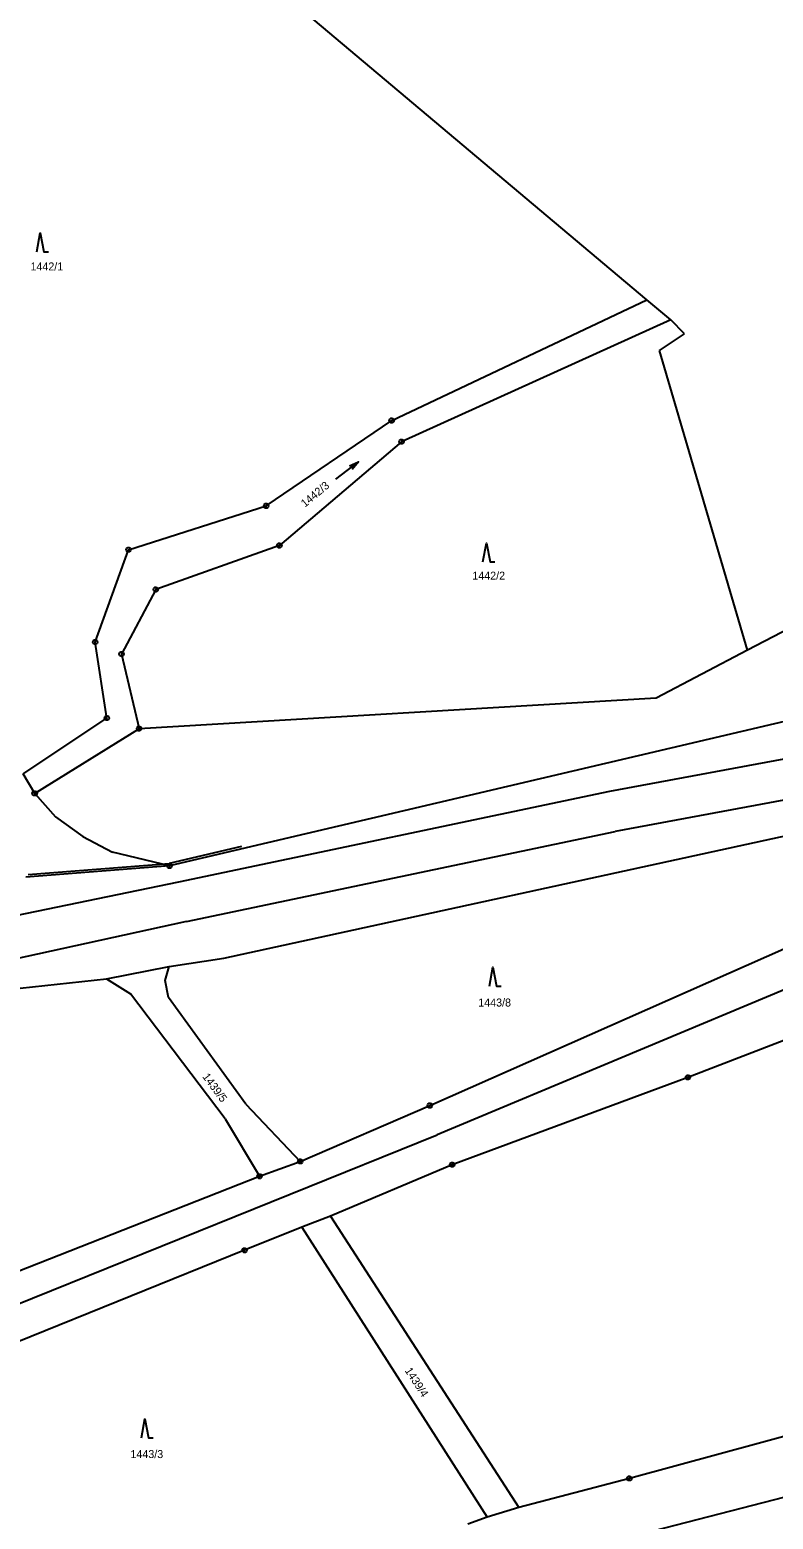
# Model space of a CAD drawing. Extents: x -779618 to -776429, y -1144546 to -1143350.
# Drawn here: x -779036.4 to -778878.5, y -1144107.3 to -1143790.9 of the extents above; entities that cross this region are included whole.
import ezdxf

# ---------------------------------------------------------------- set-up
doc = ezdxf.new("R2010")
doc.units = 0
for name, color, linetype in [('1', 7, 'Continuous'), ('2', 7, 'Continuous'), ('3', 7, 'Continuous'), ('4', 7, 'Continuous'), ('6', 7, 'Continuous'), ('8', 7, 'Continuous')]:
    doc.layers.add(name, color=color, linetype=linetype)

msp = doc.modelspace()

# ---------------------------------------------------------------- linework, layer by layer
at = {"layer": '1'}
for p, q in [((-778905.32, -1143848.25), (-779024.41, -1143748.09)), ((-778959.55, -1143873.91), (-778905.32, -1143848.25)), ((-778900.27, -1143852.49), (-778905.32, -1143848.25)), ((-778900.27, -1143852.49), (-778957.45, -1143878.42)), ((-778897.33, -1143855.5), (-778900.27, -1143852.49)), ((-778902.68, -1143859.04), (-778897.33, -1143855.5)), ((-778883.94, -1143922.67), (-778902.68, -1143859.04)), ((-778986.2, -1143892.04), (-778959.55, -1143873.91)), ((-778957.45, -1143878.42), (-778983.4, -1143900.47)), ((-779015.46, -1143901.34), (-778986.2, -1143892.04)), ((-778983.4, -1143900.47), (-779009.67, -1143909.81)), ((-779022.54, -1143920.99), (-779015.46, -1143901.34)), ((-779009.67, -1143909.81), (-779016.93, -1143923.52)), ((-778859.79, -1143910.12), (-778883.94, -1143922.67)), ((-779020.06, -1143937.12), (-779022.54, -1143920.99)), ((-778883.94, -1143922.67), (-778903.35, -1143932.91)), ((-779016.93, -1143923.52), (-779013.21, -1143939.37)), ((-778853.06, -1143932.41), (-779006.75, -1143968.53)), ((-778903.35, -1143932.91), (-779013.21, -1143939.37)), ((-779037.83, -1143948.95), (-779020.06, -1143937.12)), ((-779013.21, -1143939.37), (-779035.38, -1143953.12)), ((-779035.38, -1143953.12), (-779037.83, -1143948.95)), ((-779035.38, -1143953.12), (-779030.98, -1143958.09)), ((-779030.98, -1143958.09), (-779025.16, -1143962.28)), ((-779025.16, -1143962.28), (-779018.83, -1143965.62)), ((-778995.21, -1143988.16), (-778873.05, -1143961.47)), ((-779006.75, -1143968.53), (-779018.83, -1143965.62)), ((-779006.75, -1143968.53), (-779037.25, -1143970.89)), ((-778951.45, -1144019.43), (-778858.72, -1143978.35)), ((-779006.83, -1143989.87), (-778995.21, -1143988.16)), ((-779038.48, -1143994.53), (-779020.16, -1143992.5)), ((-779020.16, -1143992.5), (-779006.83, -1143989.87)), ((-779020.16, -1143992.5), (-779015.01, -1143995.67)), ((-779007.66, -1143992.86), (-779006.83, -1143989.87)), ((-778994.91, -1144022.25), (-779015.01, -1143995.67)), ((-779006.98, -1143996.49), (-779007.66, -1143992.86)), ((-778990.55, -1144019.15), (-779006.98, -1143996.49)), ((-778852.71, -1143996.58), (-778896.61, -1144013.46)), ((-778896.61, -1144013.46), (-778946.7, -1144032.01)), ((-778990.55, -1144019.15), (-778978.96, -1144031.32)), ((-778978.96, -1144031.32), (-778951.45, -1144019.43)), ((-778994.91, -1144022.25), (-778987.6, -1144034.47)), ((-778987.6, -1144034.47), (-778978.96, -1144031.32)), ((-778946.7, -1144032.01), (-778972.53, -1144042.97)), ((-779044.42, -1144056.76), (-778987.6, -1144034.47)), ((-778972.53, -1144042.97), (-778978.64, -1144045.3)), ((-778972.53, -1144042.97), (-778932.54, -1144104.86)), ((-778978.64, -1144045.3), (-778990.79, -1144050.19)), ((-778978.64, -1144045.3), (-778939.23, -1144106.88)), ((-778990.79, -1144050.19), (-779039.08, -1144069.74)), ((-778843.23, -1144080.83), (-778909.06, -1144098.66)), ((-778909.06, -1144098.66), (-778932.54, -1144104.86)), ((-778947.15, -1144120.83), (-778870.04, -1144101.07)), ((-778932.54, -1144104.86), (-778939.23, -1144106.88)), ((-778939.23, -1144106.88), (-778943.37, -1144108.37))]:
    msp.add_line(p, q, dxfattribs=at)
at = {"layer": '3'}
msp.add_line((-778971.41, -1143886.33), (-778966.63, -1143882.71), dxfattribs=at)
for points in [[(-779034.96, -1143838.03), (-779034.21, -1143834.03), (-779033.46, -1143838.03), (-779032.46, -1143838.03)], [(-778968.52, -1143883.52), (-778966.63, -1143882.71), (-778967.92, -1143884.32)], [(-778940.15, -1143903.95), (-778939.4, -1143899.95), (-778938.65, -1143903.95), (-778937.65, -1143903.95)], [(-778938.8, -1143994.05), (-778938.05, -1143990.05), (-778937.3, -1143994.05), (-778936.3, -1143994.05)], [(-779012.73, -1144090.02), (-779011.98, -1144086.02), (-779011.23, -1144090.02), (-779010.23, -1144090.02)]]:
    msp.add_lwpolyline(points, dxfattribs=at)
at = {"layer": '4'}
for p, q in [((-778826.44, -1143936.63), (-778913.28, -1143952.75)), ((-778824.89, -1143944.99), (-778912.1, -1143961.18)), ((-778913.28, -1143952.75), (-779004.84, -1143972.01)), ((-779003.12, -1143980.33), (-778912.1, -1143961.18)), ((-778991.42, -1143964.41), (-779006.83, -1143968.03)), ((-779036.75, -1143970.35), (-779006.83, -1143968.03)), ((-779004.84, -1143972.01), (-779044.16, -1143980.12)), ((-779003.12, -1143980.33), (-779039.97, -1143988.41))]:
    msp.add_line(p, q, dxfattribs=at)
at = {"layer": '6'}
for p in [(-778823.57, -1143972.84), (-779101.7, -1144086.88)]:
    msp.add_line(p, (-778949.91, -1144025.67), dxfattribs=at)
at = {"layer": '8'}
for p, q in [((-778959.67, -1143873.91), (-778959.43, -1143873.91)), ((-778957.57, -1143878.42), (-778957.33, -1143878.42)), ((-778986.32, -1143892.04), (-778986.08, -1143892.04)), ((-778983.52, -1143900.47), (-778983.28, -1143900.47)), ((-779015.58, -1143901.34), (-779015.34, -1143901.34)), ((-779009.79, -1143909.81), (-779009.55, -1143909.81)), ((-779022.66, -1143920.99), (-779022.42, -1143920.99)), ((-779017.05, -1143923.52), (-779016.81, -1143923.52)), ((-779020.18, -1143937.12), (-779019.94, -1143937.12)), ((-779013.33, -1143939.37), (-779013.09, -1143939.37)), ((-779035.5, -1143953.12), (-779035.26, -1143953.12)), ((-779006.87, -1143968.53), (-779006.63, -1143968.53)), ((-778896.73, -1144013.46), (-778896.49, -1144013.46)), ((-778951.57, -1144019.43), (-778951.33, -1144019.43)), ((-778979.08, -1144031.32), (-778978.84, -1144031.32)), ((-778946.82, -1144032.01), (-778946.58, -1144032.01)), ((-778987.72, -1144034.47), (-778987.48, -1144034.47)), ((-778990.91, -1144050.19), (-778990.67, -1144050.19)), ((-778909.18, -1144098.66), (-778908.94, -1144098.66))]:
    msp.add_line(p, q, dxfattribs=at)
for points in [[(-778959.4, -1143873.43), (-778959.15, -1143873.61), (-778959.05, -1143873.9), (-778959.15, -1143874.19), (-778959.4, -1143874.37), (-778959.71, -1143874.37), (-778959.96, -1143874.19), (-778960.06, -1143873.9), (-778959.96, -1143873.61), (-778959.71, -1143873.43)], [(-778957.3, -1143877.94), (-778957.05, -1143878.12), (-778956.95, -1143878.41), (-778957.05, -1143878.7), (-778957.3, -1143878.88), (-778957.61, -1143878.88), (-778957.86, -1143878.7), (-778957.96, -1143878.41), (-778957.86, -1143878.12), (-778957.61, -1143877.94)], [(-778986.05, -1143891.56), (-778985.8, -1143891.74), (-778985.7, -1143892.03), (-778985.8, -1143892.32), (-778986.05, -1143892.5), (-778986.36, -1143892.5), (-778986.61, -1143892.32), (-778986.71, -1143892.03), (-778986.61, -1143891.74), (-778986.36, -1143891.56)], [(-778983.25, -1143899.99), (-778983, -1143900.17), (-778982.9, -1143900.46), (-778983, -1143900.75), (-778983.25, -1143900.93), (-778983.56, -1143900.93), (-778983.81, -1143900.75), (-778983.91, -1143900.46), (-778983.81, -1143900.17), (-778983.56, -1143899.99)], [(-779015.31, -1143900.86), (-779015.06, -1143901.04), (-779014.96, -1143901.33), (-779015.06, -1143901.62), (-779015.31, -1143901.8), (-779015.62, -1143901.8), (-779015.87, -1143901.62), (-779015.97, -1143901.33), (-779015.87, -1143901.04), (-779015.62, -1143900.86)], [(-779009.52, -1143909.33), (-779009.27, -1143909.51), (-779009.17, -1143909.8), (-779009.27, -1143910.09), (-779009.52, -1143910.27), (-779009.83, -1143910.27), (-779010.08, -1143910.09), (-779010.18, -1143909.8), (-779010.08, -1143909.51), (-779009.83, -1143909.33)], [(-779022.39, -1143920.51), (-779022.14, -1143920.69), (-779022.04, -1143920.98), (-779022.14, -1143921.27), (-779022.39, -1143921.45), (-779022.7, -1143921.45), (-779022.95, -1143921.27), (-779023.05, -1143920.98), (-779022.95, -1143920.69), (-779022.7, -1143920.51)], [(-779016.78, -1143923.04), (-779016.53, -1143923.22), (-779016.43, -1143923.51), (-779016.53, -1143923.8), (-779016.78, -1143923.98), (-779017.09, -1143923.98), (-779017.34, -1143923.8), (-779017.44, -1143923.51), (-779017.34, -1143923.22), (-779017.09, -1143923.04)], [(-779019.91, -1143936.64), (-779019.66, -1143936.82), (-779019.56, -1143937.11), (-779019.66, -1143937.4), (-779019.91, -1143937.58), (-779020.22, -1143937.58), (-779020.47, -1143937.4), (-779020.57, -1143937.11), (-779020.47, -1143936.82), (-779020.22, -1143936.64)], [(-779013.06, -1143938.89), (-779012.81, -1143939.07), (-779012.71, -1143939.36), (-779012.81, -1143939.65), (-779013.06, -1143939.83), (-779013.37, -1143939.83), (-779013.62, -1143939.65), (-779013.72, -1143939.36), (-779013.62, -1143939.07), (-779013.37, -1143938.89)], [(-779035.23, -1143952.64), (-779034.98, -1143952.82), (-779034.88, -1143953.11), (-779034.98, -1143953.4), (-779035.23, -1143953.58), (-779035.54, -1143953.58), (-779035.79, -1143953.4), (-779035.89, -1143953.11), (-779035.79, -1143952.82), (-779035.54, -1143952.64)], [(-779006.6, -1143968.05), (-779006.35, -1143968.23), (-779006.25, -1143968.52), (-779006.35, -1143968.81), (-779006.6, -1143968.99), (-779006.91, -1143968.99), (-779007.16, -1143968.81), (-779007.26, -1143968.52), (-779007.16, -1143968.23), (-779006.91, -1143968.05)], [(-778896.46, -1144012.98), (-778896.21, -1144013.16), (-778896.11, -1144013.45), (-778896.21, -1144013.74), (-778896.46, -1144013.92), (-778896.77, -1144013.92), (-778897.02, -1144013.74), (-778897.12, -1144013.45), (-778897.02, -1144013.16), (-778896.77, -1144012.98)], [(-778951.3, -1144018.95), (-778951.05, -1144019.13), (-778950.95, -1144019.42), (-778951.05, -1144019.71), (-778951.3, -1144019.89), (-778951.61, -1144019.89), (-778951.86, -1144019.71), (-778951.96, -1144019.42), (-778951.86, -1144019.13), (-778951.61, -1144018.95)], [(-778978.81, -1144030.84), (-778978.56, -1144031.02), (-778978.46, -1144031.31), (-778978.56, -1144031.6), (-778978.81, -1144031.78), (-778979.12, -1144031.78), (-778979.37, -1144031.6), (-778979.47, -1144031.31), (-778979.37, -1144031.02), (-778979.12, -1144030.84)], [(-778946.55, -1144031.53), (-778946.3, -1144031.71), (-778946.2, -1144032), (-778946.3, -1144032.29), (-778946.55, -1144032.47), (-778946.86, -1144032.47), (-778947.11, -1144032.29), (-778947.21, -1144032), (-778947.11, -1144031.71), (-778946.86, -1144031.53)], [(-778987.45, -1144033.99), (-778987.2, -1144034.17), (-778987.1, -1144034.46), (-778987.2, -1144034.75), (-778987.45, -1144034.93), (-778987.76, -1144034.93), (-778988.01, -1144034.75), (-778988.11, -1144034.46), (-778988.01, -1144034.17), (-778987.76, -1144033.99)], [(-778990.64, -1144049.71), (-778990.39, -1144049.89), (-778990.29, -1144050.18), (-778990.39, -1144050.47), (-778990.64, -1144050.65), (-778990.95, -1144050.65), (-778991.2, -1144050.47), (-778991.3, -1144050.18), (-778991.2, -1144049.89), (-778990.95, -1144049.71)], [(-778908.91, -1144098.18), (-778908.66, -1144098.36), (-778908.56, -1144098.65), (-778908.66, -1144098.94), (-778908.91, -1144099.12), (-778909.22, -1144099.12), (-778909.47, -1144098.94), (-778909.57, -1144098.65), (-778909.47, -1144098.36), (-778909.22, -1144098.18)]]:
    msp.add_lwpolyline(points, close=True, dxfattribs=at)

# ---------------------------------------------------------------- texts
at = {"layer": '2'}
for s, p in [('1442/1', (-779036.28, -1143842.02)), ('1442/2', (-778942.41, -1143907.71)), ('1443/8', (-778941.15, -1143998.4)), ('1443/3', (-779015.04, -1144094.33))]:
    msp.add_text(s, height=1.7, dxfattribs=at).set_placement(p)
for s, rotation, p in [('1442/3', 39.8206, (-778977.97, -1143892.44)), ('1439/5', 306.4751, (-778999.84, -1144013.32)), ('1439/4', 303.0947, (-778956.84, -1144075.74))]:
    msp.add_text(s, height=1.7, rotation=rotation, dxfattribs=at).set_placement(p)

doc.saveas('drawing.dxf')
